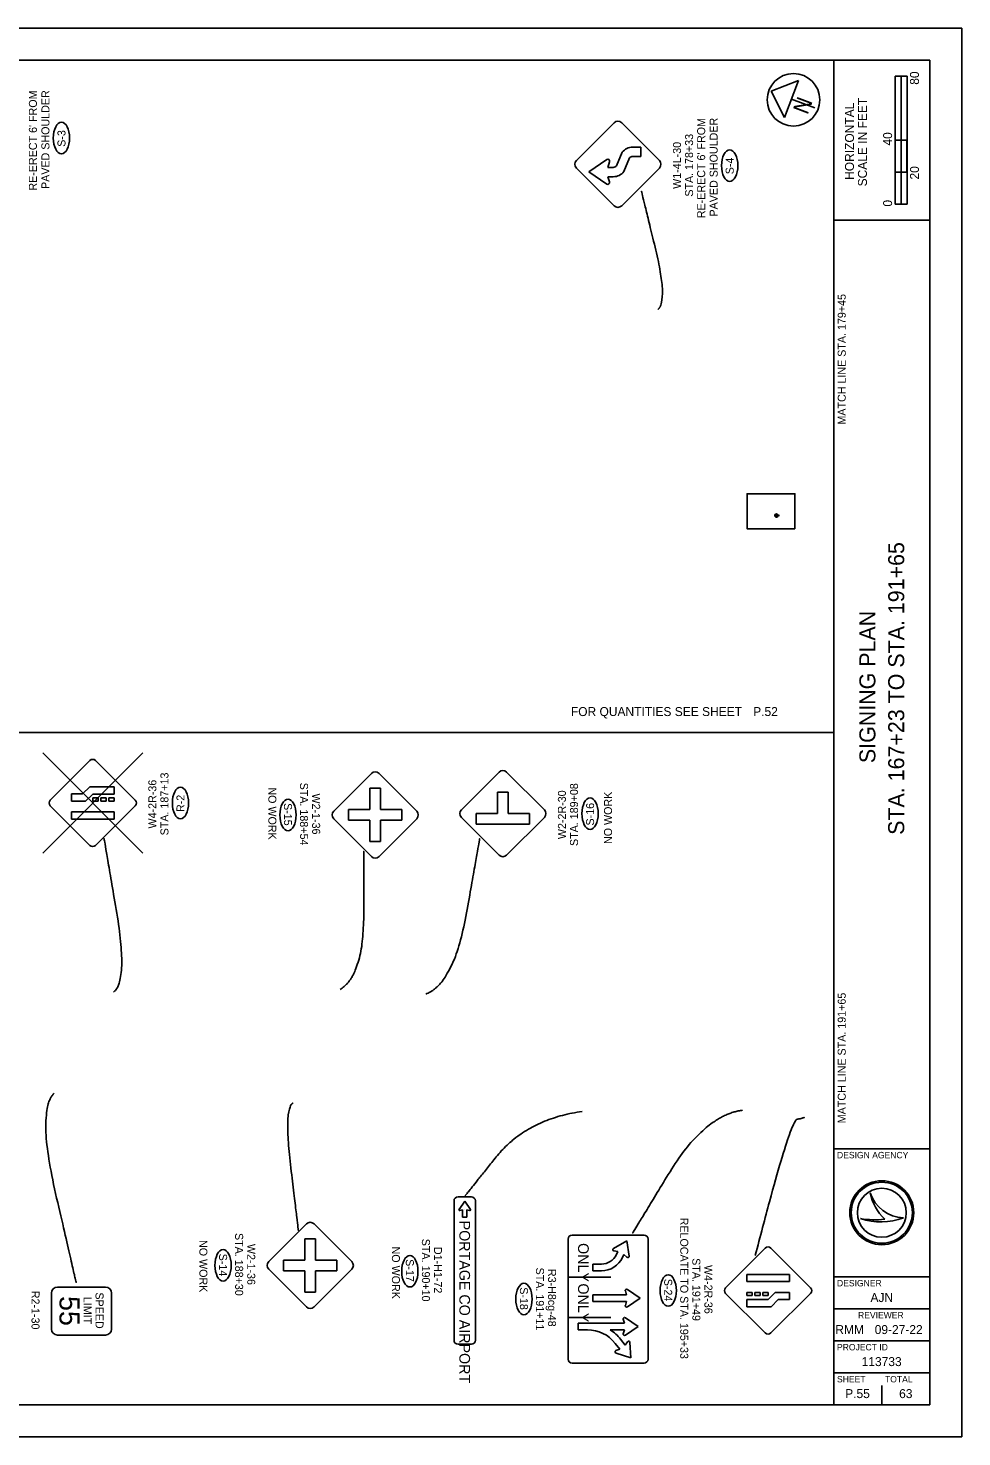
# Model space of a CAD drawing. Extents: x 0 to 6331, y 0 to 440.
# Drawn here: x 388.3 to 680, y 0 to 440 of the extents above; entities that cross this region are included whole.
import ezdxf

# ---------------------------------------------------------------- set-up
doc = ezdxf.new("R2010")
doc.units = 0
for name, color, linetype in [('PM_P_Dotted_Line', 7, 'Continuous'), ('PM_P_Edge_Line', 7, 'Continuous'), ('PM_X_CL_Double_Solid', 7, 'Continuous'), ('PM_X_Edge_Line', 7, 'Continuous'), ('PM_X_Lane_Line', 7, 'Continuous'), ('PV_P_Shoulder', 7, 'Continuous'), ('PV_X_EOP', 7, 'Continuous'), ('PV_X_Shoulder', 7, 'Continuous'), ('SN_X_Text', 7, 'Continuous')]:
    doc.layers.add(name, color=color, linetype=linetype)

msp = doc.modelspace()

# ---------------------------------------------------------------- linework, layer by layer
at = {"layer": 'PM_P_Dotted_Line'}
for p, q in [((573.92, 401.25), (572.11, 396.99)), ((579.71, 402.86), (577.21, 402.86)), ((579.71, 399.94), (579.71, 402.86)), ((569.05, 398.95), (563.46, 395.13)), ((569.05, 398.95), (569.05, 398.95)), ((569.36, 396.51), (569.93, 398.29)), ((571.13, 396.51), (569.36, 396.51)), ((574.42, 395.2), (576.22, 399.46)), ((577.21, 399.94), (579.71, 399.94)), ((563.46, 395.13), (569.05, 391.32)), ((569.93, 391.98), (569.41, 393.59)), ((569.41, 393.59), (571.13, 393.59)), ((424.12, 182.36), (392.87, 213.61)), ((392.87, 182.36), (424.12, 213.61)), ((405.35, 200.81), (407.56, 203.02)), ((407.56, 203.02), (415.16, 203.02)), ((415.16, 203.02), (415.16, 200.77)), ((498.41, 202.57), (495.08, 202.57)), ((495.08, 202.57), (495.08, 195.91)), ((498.41, 195.91), (498.41, 202.57)), ((401.83, 198.56), (401.83, 200.81)), ((401.83, 200.81), (405.35, 200.81)), ((406.28, 198.56), (401.83, 198.56)), ((408.49, 200.77), (406.28, 198.56)), ((415.16, 200.77), (408.49, 200.77)), ((408.49, 198.56), (408.49, 199.56)), ((408.49, 199.56), (410.16, 199.56)), ((410.16, 198.56), (408.49, 198.56)), ((410.16, 199.56), (410.16, 198.56)), ((412.66, 199.56), (410.99, 199.56)), ((410.99, 199.56), (410.99, 198.56)), ((410.99, 198.56), (412.66, 198.56)), ((412.66, 198.56), (412.66, 199.56)), ((413.49, 198.56), (413.49, 199.56)), ((413.49, 199.56), (415.16, 199.56)), ((415.16, 198.56), (413.49, 198.56)), ((415.16, 199.56), (415.16, 198.56)), ((538.29, 201.33), (534.96, 201.33)), ((534.96, 201.33), (534.96, 194.66)), ((538.29, 194.66), (538.29, 201.33)), ((415.16, 195.19), (401.83, 195.19)), ((401.83, 195.19), (401.83, 192.94)), ((415.16, 192.94), (415.16, 195.19)), ((495.08, 195.91), (488.41, 195.91)), ((488.41, 195.91), (488.41, 192.57)), ((505.08, 195.91), (498.41, 195.91)), ((505.08, 192.57), (505.08, 195.91)), ((534.96, 194.66), (528.29, 194.66)), ((528.29, 194.66), (528.29, 191.33)), ((544.96, 194.66), (538.29, 194.66)), ((544.96, 191.33), (544.96, 194.66)), ((401.83, 192.94), (415.16, 192.94)), ((488.41, 192.57), (495.08, 192.57)), ((495.08, 192.57), (495.08, 185.91)), ((498.41, 185.91), (498.41, 192.57)), ((498.41, 192.57), (505.08, 192.57)), ((528.29, 191.33), (544.96, 191.33)), ((495.08, 185.91), (498.41, 185.91)), ((522.92, 71.05), (524.69, 73.57)), ((524.03, 70.92), (523.22, 70.66)), ((524.03, 70.91), (524.03, 70.92)), ((524.03, 68.57), (524.03, 70.91)), ((524.69, 73.57), (526.46, 71.05)), ((524.69, 71), (524.69, 71)), ((526.17, 70.66), (525.36, 70.92)), ((525.36, 68.57), (524.03, 68.57)), ((478.13, 61.88), (474.8, 61.88)), ((474.8, 61.88), (474.8, 55.21)), ((478.13, 55.21), (478.13, 61.88)), ((474.8, 55.21), (468.13, 55.21)), ((468.13, 55.21), (468.13, 51.88)), ((484.8, 55.21), (478.13, 55.21)), ((484.8, 51.88), (484.8, 55.21)), ((468.13, 51.88), (474.8, 51.88)), ((474.8, 51.88), (474.8, 45.21)), ((478.13, 45.21), (478.13, 51.88)), ((478.13, 51.88), (484.8, 51.88)), ((626.13, 50.74), (612.8, 50.74)), ((612.8, 50.74), (612.8, 48.49)), ((612.8, 48.49), (626.13, 48.49)), ((626.13, 48.49), (626.13, 50.74)), ((474.8, 45.21), (478.13, 45.21)), ((612.8, 44.11), (612.8, 45.11)), ((612.8, 45.11), (614.47, 45.11)), ((614.47, 44.11), (612.8, 44.11)), ((614.47, 45.11), (614.47, 44.11)), ((616.97, 45.11), (615.3, 45.11)), ((615.3, 45.11), (615.3, 44.11)), ((615.3, 44.11), (616.97, 44.11)), ((616.97, 44.11), (616.97, 45.11)), ((617.8, 45.11), (619.47, 45.11)), ((617.8, 44.11), (617.8, 45.11)), ((619.47, 44.11), (617.8, 44.11)), ((619.47, 42.9), (621.68, 45.11)), ((619.47, 45.11), (619.47, 44.11)), ((621.68, 45.11), (626.13, 45.11)), ((626.13, 45.11), (626.13, 42.86)), ((612.8, 40.65), (612.8, 42.9)), ((612.8, 42.9), (619.47, 42.9)), ((620.4, 40.65), (612.8, 40.65)), ((622.61, 42.86), (620.4, 40.65)), ((626.13, 42.86), (622.61, 42.86))]:
    msp.add_line(p, q, dxfattribs=at)
for points in [[(571.38, 410.45), (559.6, 398.66)], [(585.52, 398.66), (573.74, 410.45)], [(559.6, 396.3), (571.38, 384.52)], [(573.74, 384.52), (585.52, 396.3)], [(395.24, 198.87), (407.61, 211.24)], [(409.38, 211.24), (421.75, 198.87)], [(495.57, 207.2), (483.78, 195.42)], [(509.71, 195.42), (497.93, 207.2)], [(523.66, 195.84), (535.44, 207.63)], [(537.8, 207.63), (549.59, 195.84)], [(407.61, 184.72), (395.24, 197.1)], [(421.75, 197.1), (409.38, 184.72)], [(483.78, 193.06), (495.57, 181.28)], [(497.93, 181.28), (509.71, 193.06)], [(535.44, 181.7), (523.66, 193.48)], [(549.59, 193.48), (537.8, 181.7)], [(526.78, 74.96), (522.61, 74.96)], [(521.36, 73.71), (521.36, 30.18)], [(525.36, 70.91), (525.36, 68.57)], [(528.03, 30.18), (528.03, 73.71)], [(475.28, 66.51), (463.5, 54.72)], [(489.43, 54.72), (477.64, 66.51)], [(606.21, 46.58), (618.58, 58.95)], [(620.35, 58.95), (632.73, 46.58)], [(463.5, 52.36), (475.28, 40.58)], [(477.64, 40.58), (489.43, 52.36)], [(395.62, 44.91), (395.62, 33.66)], [(412.5, 46.78), (397.5, 46.78)], [(414.37, 33.66), (414.37, 44.91)], [(618.58, 32.44), (606.21, 44.81)], [(632.73, 44.81), (620.35, 32.44)], [(397.5, 31.78), (412.5, 31.78)], [(522.61, 28.93), (526.78, 28.93)]]:
    msp.add_lwpolyline(points, dxfattribs=at)
for centre, radius, start, end in [((572.56, 409.27), 1.67, 45, 135), ((577.21, 398.69), 4.17, 90, 142.125), ((560.77, 397.48), 1.67, 135, 225), ((569.37, 398.47), 0.583, 342.2271, 124.326), ((571.13, 397.76), 1.25, 270, 322.125), ((577.21, 398.69), 1.25, 90, 142.125), ((584.34, 397.48), 1.67, 315, 45), ((569.37, 391.8), 0.583, 235.6735, 17.7698), ((571.13, 397.76), 4.17, 270, 322.125), ((572.56, 385.7), 1.67, 225, 315), ((408.49, 210.36), 1.25, 45, 135), ((496.75, 206.03), 1.67, 45, 135), ((536.62, 206.45), 1.67, 45, 135), ((396.12, 197.98), 1.25, 135, 225), ((420.87, 197.98), 1.25, 315, 45), ((484.96, 194.24), 1.67, 135, 225), ((508.53, 194.24), 1.67, 315, 45), ((524.84, 194.66), 1.67, 135, 225), ((548.41, 194.66), 1.67, 315, 45), ((408.49, 185.61), 1.25, 225, 315), ((496.75, 182.45), 1.67, 225, 315), ((536.62, 182.88), 1.67, 225, 315), ((522.61, 73.71), 1.25, 90, 180), ((526.78, 73.71), 1.25, 360, 90), ((523.14, 70.91), 0.259, 144.9207, 287.6378), ((526.25, 70.91), 0.259, 252.3622, 35.0792), ((476.46, 65.33), 1.67, 45, 135), ((619.47, 58.07), 1.25, 45, 135), ((464.68, 53.54), 1.67, 135, 225), ((488.25, 53.54), 1.67, 315, 45), ((397.5, 44.91), 1.88, 90, 180), ((412.5, 44.91), 1.88, 0, 90), ((607.09, 45.7), 1.25, 135, 225), ((631.84, 45.7), 1.25, 315, 45), ((476.46, 41.76), 1.67, 225, 315), ((397.5, 33.66), 1.88, 180, 270), ((412.5, 33.66), 1.88, 270, 0), ((619.47, 33.32), 1.25, 225, 315), ((522.61, 30.18), 1.25, 180, 270), ((526.78, 30.18), 1.25, 270, 0)]:
    msp.add_arc(centre, radius, start, end, dxfattribs=at)
at = {"layer": 'PM_P_Edge_Line'}
for p, q in [((571.14, 58.83), (575.33, 61.24)), ((572.57, 57.87), (571.29, 58.05)), ((572.11, 56.92), (572.57, 57.87)), ((575.33, 61.24), (576.09, 56.47)), ((564.7, 51.87), (564.7, 53.95)), ((564.7, 53.95), (567.41, 53.95)), ((574.45, 56.98), (573.99, 56.02)), ((575.39, 56.1), (574.45, 56.98)), ((570.33, 49.84), (556.99, 49.84)), ((567.41, 51.87), (564.7, 51.87)), ((575.26, 44.37), (564.7, 44.37)), ((564.7, 44.37), (564.7, 42.29)), ((574.88, 45.6), (575.26, 44.37)), ((579.49, 43.33), (575.51, 46.07)), ((564.7, 42.29), (575.26, 42.29)), ((575.26, 42.29), (574.88, 41.06)), ((575.51, 40.59), (579.49, 43.33)), ((570.33, 37.23), (556.99, 37.23)), ((574.64, 35.52), (560.12, 35.52)), ((560.12, 35.52), (560.12, 33.43)), ((574.25, 36.74), (574.64, 35.52)), ((578.87, 34.47), (574.89, 37.21)), ((560.12, 33.43), (563.04, 33.43)), ((570.13, 33.43), (574.64, 33.43)), ((574.64, 33.43), (574.25, 32.2)), ((574.89, 31.73), (578.87, 34.47)), ((571.74, 29.19), (573.15, 27.38)), ((573.15, 27.38), (571.95, 26.92)), ((574.79, 28.66), (573.38, 30.47)), ((575.53, 29.72), (574.79, 28.66)), ((576.58, 24.68), (576.28, 29.51)), ((571.97, 26.14), (576.58, 24.68))]:
    msp.add_line(p, q, dxfattribs=at)
for points in [[(556.99, 61.77), (556.99, 24.27)], [(580.74, 63.02), (558.24, 63.02)], [(581.99, 24.27), (581.99, 61.77)], [(558.24, 23.02), (580.74, 23.02)]]:
    msp.add_lwpolyline(points, dxfattribs=at)
for centre, radius, start, end in [((558.24, 61.77), 1.25, 90, 180), ((580.74, 61.77), 1.25, 0, 90), ((571.35, 58.47), 0.417, 120.001, 261.8791), ((567.41, 59.16), 5.21, 270, 334.5173), ((567.41, 59.16), 7.29, 270, 334.5173), ((575.67, 56.4), 0.417, 227.1555, 9.0336), ((575.27, 45.72), 0.417, 55.4837, 197.3618), ((575.27, 40.93), 0.417, 162.6382, 304.5163), ((574.65, 36.87), 0.417, 55.4837, 197.3618), ((563.04, 22.39), 11.04, 37.9857, 90), ((563.04, 22.39), 13.12, 37.9857, 57.2745), ((574.65, 32.08), 0.417, 162.6382, 304.5163), ((572.09, 26.53), 0.417, 110.6239, 252.502), ((575.87, 29.48), 0.417, 3.4694, 145.3475), ((558.24, 24.27), 1.25, 180, 270), ((580.74, 24.27), 1.25, 270, 0)]:
    msp.add_arc(centre, radius, start, end, dxfattribs=at)
at = {"layer": 'PM_X_CL_Double_Solid'}
msp.add_lwpolyline([(0, 0), (680, 0), (680, 440), (0, 440)], close=True, dxfattribs=at)
at = {"layer": 'PM_X_Edge_Line'}
for p, q in [((640, 10), (640, 430)), ((640, 380), (670, 380)), ((640, 90), (670, 90)), ((640, 50), (670, 50)), ((640, 40), (670, 40)), ((640, 30), (670, 30)), ((640, 20), (670, 20))]:
    msp.add_line(p, q, dxfattribs=at)
msp.add_lwpolyline([(30, 430), (670, 430), (670, 10), (30, 10)], close=True, dxfattribs=at)
at = {"layer": 'PM_X_Lane_Line'}
for p, q in [((659.13, 385), (659.13, 425)), ((662.88, 425), (659.13, 425)), ((659.13, 405), (659.13, 425)), ((659.13, 425), (661, 425)), ((661, 425), (661.02, 425)), ((661.02, 425), (661.02, 405)), ((662.88, 425), (662.88, 385)), ((661.02, 405), (659.13, 405)), ((662.87, 405), (661, 405)), ((661, 405), (661, 395)), ((662.87, 395), (662.87, 405)), ((661, 395), (659.13, 395)), ((659.13, 395), (659.13, 385)), ((661, 385), (661, 395)), ((661, 395), (662.87, 395)), ((662.88, 385), (659.13, 385)), ((659.13, 385), (661, 385)), ((651.35, 76.19), (651.35, 76.19)), ((648.34, 68.19), (648.34, 68.19)), ((655, 70), (655, 70)), ((661.75, 68.37), (661.75, 68.37)), ((647.5, 13.5), (647.5, 13.5)), ((655, 10), (655, 16))]:
    msp.add_line(p, q, dxfattribs=at)
for radius in [10, 9.54, 9.54, 7.64]:
    msp.add_circle((655, 70), radius, dxfattribs=at)
for centre, radius, start, end in [((662.32, 79.95), 11.6, 198.9257, 198.9319), ((666.93, 79.4), 15.91, 191.6379, 191.6421), ((662.32, 79.95), 11.6, 198.9319, 267.1657), ((666.93, 79.4), 15.91, 191.6421, 226.0947), ((654.79, 87.4), 20.26, 251.4576, 290.0832), ((652.96, 93.09), 25.32, 259.4964, 259.4995), ((654.79, 87.4), 20.26, 251.4527, 251.4576), ((652.96, 93.09), 25.32, 259.4995, 276.6672)]:
    msp.add_arc(centre, radius, start, end, dxfattribs=at)
at = {"layer": 'PV_X_EOP'}
for p, q in [((628.98, 423.62), (620.42, 420.28)), ((624.63, 412.11), (628.98, 423.62)), ((620.42, 420.28), (624.63, 412.11)), ((626.81, 417.86), (634.04, 415.13)), ((621.57, 287.76), (622.61, 287.76)), ((622.09, 287.76), (623.08, 287.76))]:
    msp.add_line(p, q, dxfattribs=at)
for points in [[(640, 220), (30, 220), (30, 430), (640, 430)], [(627.88, 283.63), (612.9, 283.63), (612.9, 294.57), (627.88, 294.57)], [(640, 10), (30, 10), (30, 220), (640, 220)]]:
    msp.add_lwpolyline(points, close=True, dxfattribs=at)
for centre, radius in [((627.41, 417.63), 8.2), ((622.09, 287.76), 0.521)]:
    msp.add_circle(centre, radius, dxfattribs=at)
for centre, major_axis in [((398.73, 405.67), (0, 4.93)), ((607.48, 397.07), (0, 4.93)), ((435.91, 197.98), (0, 4.93)), ((469.5, 194.24), (0, -4.93)), ((563.87, 194.66), (0, 4.93)), ((449.22, 53.54), (0, -4.93)), ((507.56, 51.73), (0, -4.93)), ((588.27, 45.7), (0, -4.93)), ((543.2, 43.02), (0, -4.93))]:
    msp.add_ellipse(centre, major_axis=major_axis, ratio=0.516454, dxfattribs=at)
for points in [[(585.07, 352.14), (588.31, 354.7), (579.92, 389.02), (579.92, 389.02)], [(414.94, 138.87), (419.65, 142.31), (412.04, 186.83), (412.04, 186.83)], [(512.51, 138.29), (521.4, 141.53), (529.36, 186.76), (529.36, 186.76)], [(485.76, 139.75), (493.16, 144.17), (493.16, 182.82), (493.16, 182.82)], [(396.48, 107.38), (390.88, 102.13), (403.31, 48.27), (403.31, 48.27)], [(471.08, 104.29), (468.14, 102.88), (472.72, 64.54), (472.72, 64.54)], [(561.4, 101.63), (543.93, 99.17), (524.89, 75.36), (524.89, 75.36)], [(611.5, 102.03), (599.47, 100.39), (577.21, 63.7), (577.21, 63.7)], [(615.47, 56.63), (626.23, 98.54), (630.76, 99.73), (630.76, 99.73)]]:
    msp.add_open_spline(points, degree=2, dxfattribs=at)
at = {"layer": 'PV_X_Shoulder'}
msp.add_circle((627.41, 417.63), 8.2, dxfattribs=at)

# ---------------------------------------------------------------- texts
at = {"layer": 'PM_P_Dotted_Line'}
for s, height, p in [('PORTAGE CO AIRPORT', 3.3333, (523.03, 67.52)), ('SPEED', 2.5, (409.37, 45.11)), ('55', 6.25, (398.12, 43.96)), ('LIMIT', 2.5, (405.62, 43.71))]:
    msp.add_text(s, height=height, rotation=270, dxfattribs=at).set_placement(p)
at = {"layer": 'PM_P_Edge_Line'}
for p in [(560.12, 60.51), (560.12, 47.91)]:
    msp.add_text('ONLY', height=3.333, rotation=270, dxfattribs=at).set_placement(p)
at = {"layer": 'PM_X_Lane_Line'}
for s, height, p in [('80', 2.8, (666.61, 422.33)), ('SCALE IN FEET', 2.8, (650.35, 390.58)), ('HORIZONTAL', 2.8, (646.3, 392.61)), ('40', 2.8, (658.21, 403.33)), ('20', 2.8, (666.61, 392.73)), ('0', 2.8, (658.21, 384.27)), ('STA. 167+23 TO STA. 191+65', 5, (662, 188.03)), ('SIGNING PLAN', 5, (653, 210.44))]:
    msp.add_text(s, height=height, rotation=90, dxfattribs=at).set_placement(p)
for s, height, p in [('DESIGN AGENCY', 2, (641, 87)), ('DESIGNER', 2, (641, 47)), ('AJN', 2.8, (651.46, 42.1)), ('REVIEWER', 2, (647.57, 37)), ('RMM', 2.8, (640.48, 32.1)), ('09-27-22', 2.8, (652.78, 32.1)), ('PROJECT ID', 2, (641, 27)), ('113733', 2.8, (648.71, 22.1)), ('SHEET', 2, (641, 17)), ('TOTAL', 2, (656, 17)), ('P.55', 2.8, (643.56, 12.1)), ('63', 2.8, (660.41, 12.1))]:
    msp.add_text(s, height=height, dxfattribs=at).set_placement(p)
at = {"layer": 'PV_P_Shoulder'}
msp.add_text('R3-H8cg-48', height=2.5, rotation=270, dxfattribs=at).set_placement((550.74, 52.44))
at = {"layer": 'PV_X_EOP'}
for s, height, rotation, p in [('N', 5, 69.2752, (631.79, 412.74)), ('S-3', 2.5, 90, (399.98, 402.95)), ('S-4', 2.5, 90, (608.73, 394.37)), ('MATCH LINE STA. 179+45', 2.5, 90, (643.73, 316.18)), ('NO WORK', 2.5, 270, (463.36, 202.85)), ('R-2', 2.5, 90, (437.16, 195.16)), ('NO WORK', 2.5, 90, (570.72, 185.17)), ('S-15', 2.5, 270, (468.25, 197.96)), ('S-16', 2.5, 90, (565.12, 190.95)), ('MATCH LINE STA. 191+65', 2.5, 90, (643.73, 97.94)), ('NO WORK', 2.5, 270, (441.81, 61.47)), ('NO WORK', 2.5, 270, (501.96, 59.43)), ('S-14', 2.5, 270, (447.97, 57.21)), ('S-17', 2.5, 270, (506.31, 55.49)), ('S-24', 2.5, 270, (587.02, 49.36)), ('S-18', 2.5, 270, (541.95, 46.72))]:
    msp.add_text(s, height=height, rotation=rotation, dxfattribs=at).set_placement(p)
for s, height, p in [('P.55', 0.0656, (622, 287.56)), ('1', 0.0656, (622.07, 287.89)), ('Drawing', 0.0656, (622.74, 287.89)), ('1:40', 0.0656, (622.74, 287.56)), ('FOR QUANTITIES SEE SHEET ', 2.8, (557.87, 225.14)), ('P.52', 2.8, (614.82, 225.14))]:
    msp.add_text(s, height=height, dxfattribs=at).set_placement(p)
at = {"layer": 'SN_X_Text'}
for s, rotation, p in [("RE-ERECT 6' FROM ", 90, (391.06, 389.26)), ('PAVED SHOULDER', 90, (394.96, 389.77)), ("RE-ERECT 6' FROM ", 90, (599.82, 380.65)), ('PAVED SHOULDER', 90, (603.72, 381.17)), ('STA. 178+33', 90, (596.04, 387.37)), ('W1-4L-30', 90, (592.26, 389.8)), ('STA. 187+13', 90, (432.15, 187.87)), ('W4-2R-36', 90, (428.37, 190.01)), ('STA. 188+54', 270, (473.26, 204.33)), ('STA. 189+08', 90, (560.1, 184.54)), ('W2-1-36', 270, (477.04, 200.95)), ('W2-2R-30', 90, (556.32, 186.69)), ('RELOCATE TO STA. 195+33', 270, (592.03, 68.46)), ('STA. 188+30', 270, (452.98, 63.67)), ('STA. 190+10', 270, (511.33, 61.86)), ('W2-1-36', 270, (456.76, 60.26)), ('D1-H1-72', 270, (515.11, 59.31)), ('STA. 191+49', 270, (595.81, 55.8)), ('W4-2R-36', 270, (599.59, 53.67)), ('STA. 191+11', 270, (546.96, 52.86)), ('R2-1-30', 270, (389.37, 45.61))]:
    msp.add_text(s, height=2.5, rotation=rotation, dxfattribs=at).set_placement(p)

doc.saveas('drawing.dxf')
